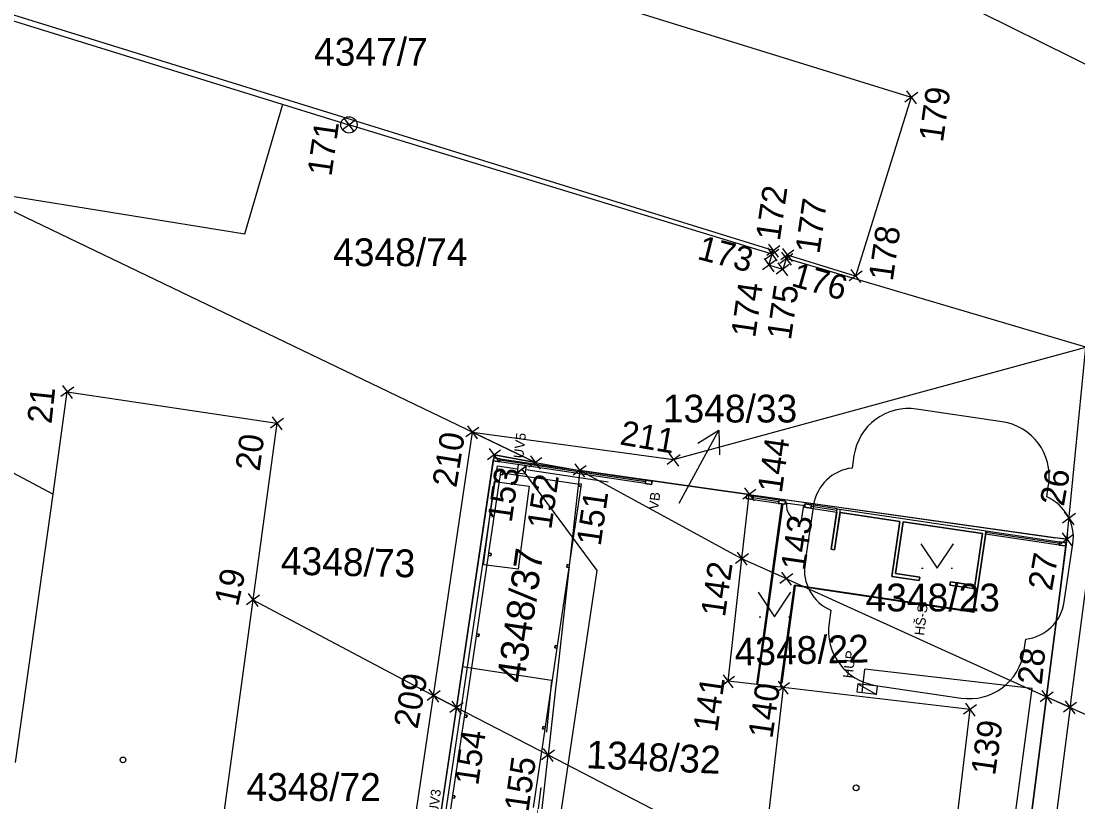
# Model space of a CAD drawing. Extents: x -735036 to -734743, y -1144813 to -1144181.
# Drawn here: x -734897 to -734832.3, y -1144527.8 to -1144480 of the extents above; entities that cross this region are included whole.
import ezdxf

# ---------------------------------------------------------------- set-up
doc = ezdxf.new("R2010")
doc.units = 0
for name, color, linetype in [('A3_BOURANÉ OBJEKTY', 7, 'Continuous'), ('A3_Netisk', 7, 'Continuous'), ('A3_ODVODŇOVACÍ ŽLAB', 7, 'Continuous'), ('A3_SIT_OBJEKTY_N01', 7, 'Continuous'), ('A3_SIT_PNB', 7, 'Continuous'), ('CKKOTY', 7, 'Continuous'), ('CKPLYN_POTRUBI_NT_PODZ_N', 7, 'Continuous'), ('CKTEXTY_MALE', 7, 'Continuous'), ('Groma (60)', 7, 'Continuous'), ('hranice pl. určené SŽDC', 7, 'Continuous'), ('Katastr_HRANICE DRÁHY', 7, 'Continuous'), ('Katastr_Hranice parcel', 7, 'Continuous'), ('Katastr_Parcelní čísla', 7, 'Continuous'), ('Katastr_Značky kultur', 7, 'Continuous'), ('SO05_CKKANALIZACE_JEDNOTNA_PODZ_N', 7, 'Continuous'), ('ZÁBORY_dočasné', 7, 'Continuous')]:
    doc.layers.add(name, color=color, linetype=linetype)

# ---------------------------------------------------------------- blocks, each defined once
blk = doc.blocks.new('POINT_DISPLAY')
for p, q in [((-0.35, -0.35), (0.35, 0.35)), ((-0.35, 0.35), (0.35, -0.35))]:
    blk.add_line(p, q)

msp = doc.modelspace()

# ---------------------------------------------------------------- linework, layer by layer
msp.add_line((-734866.625, -1144507.658), (-734866.057, -1144507.237))
for points in [[(-734866.625, -1144507.658), (-734866.13, -1144507.731), (-734866.057, -1144507.237), (-734866.551, -1144507.163)], [(-734866.625, -1144507.658), (-734866.13, -1144507.731), (-734866.057, -1144507.237)]]:
    msp.add_lwpolyline(points, close=True)
at = {"layer": 'A3_BOURANÉ OBJEKTY'}
msp.add_lwpolyline([(-734866.552, -1144513.548), (-734868.669, -1144513.299), (-734867.996, -1144508.198), (-734865.894, -1144508.483)], close=True, dxfattribs=at)
for points in [[(-734869.977, -1144519.507), (-734864.523, -1144520.336), (-734864.819, -1144523.525)], [(-734865.166, -1144526.906), (-734865.978, -1144533.409), (-734871.807, -1144532.846)]]:
    msp.add_lwpolyline(points, dxfattribs=at)
at = {"layer": 'A3_Netisk'}
msp.add_line((-734838.465, -1144514.774), (-734837.936, -1144511.213), dxfattribs=at)
at = {"layer": 'A3_ODVODŇOVACÍ ŽLAB'}
for points in [[(-734870.972, -1144528.414), (-734867.824, -1144507.227), (-734866.588, -1144507.411)], [(-734861.049, -1144508.234), (-734866.093, -1144507.484)]]:
    msp.add_lwpolyline(points, dxfattribs=at)
at = {"layer": 'A3_SIT_OBJEKTY_N01'}
for p, q in [((-734867.491, -1144507.64), (-734867.62, -1144507.621)), ((-734867.487, -1144507.681), (-734867.483, -1144507.651)), ((-734862.694, -1144508.352), (-734862.823, -1144508.333)), ((-734851.963, -1144520.613), (-734850.421, -1144509.56)), ((-734850.371, -1144509.567), (-734851.914, -1144520.619)), ((-734850.626, -1144509.529), (-734850.597, -1144509.332)), ((-734850.23, -1144509.588), (-734850.626, -1144509.529)), ((-734850.597, -1144509.332), (-734850.201, -1144509.39)), ((-734850.421, -1144509.56), (-734850.371, -1144509.567)), ((-734850.201, -1144509.39), (-734850.23, -1144509.588)), ((-734849.043, -1144509.765), (-734849.014, -1144509.567)), ((-734848.648, -1144509.823), (-734849.043, -1144509.765)), ((-734849.014, -1144509.567), (-734848.618, -1144509.626)), ((-734848.618, -1144509.626), (-734848.648, -1144509.823)), ((-734847.403, -1144512.334), (-734847.036, -1144509.861)), ((-734846.867, -1144510.088), (-734847.205, -1144512.363)), ((-734847.036, -1144509.861), (-734837.936, -1144511.213)), ((-734843.207, -1144510.632), (-734846.867, -1144510.088)), ((-734843.707, -1144513.995), (-734843.207, -1144510.632)), ((-734843.01, -1144510.661), (-734843.48, -1144513.826)), ((-734838.163, -1144511.381), (-734843.01, -1144510.661)), ((-734838.633, -1144514.546), (-734838.163, -1144511.381)), ((-734837.936, -1144511.213), (-734838.465, -1144514.774)), ((-734847.205, -1144512.363), (-734847.403, -1144512.334)), ((-734842.026, -1144514.245), (-734843.707, -1144513.995)), ((-734843.48, -1144513.826), (-734841.996, -1144514.047)), ((-734841.996, -1144514.047), (-734842.026, -1144514.245)), ((-734850.488, -1144520.532), (-734849.65, -1144514.527)), ((-734849.607, -1144514.584), (-734850.438, -1144520.538)), ((-734849.65, -1144514.527), (-734838.72, -1144516.151)), ((-734838.678, -1144516.208), (-734849.607, -1144514.584)), ((-734840.146, -1144514.524), (-734840.117, -1144514.326)), ((-734838.465, -1144514.774), (-734840.146, -1144514.524)), ((-734840.117, -1144514.326), (-734838.633, -1144514.546)), ((-734838.72, -1144516.151), (-734838.514, -1144514.766)), ((-734838.465, -1144514.774), (-734838.678, -1144516.208)), ((-734838.514, -1144514.766), (-734838.465, -1144514.774)), ((-734851.914, -1144520.619), (-734851.963, -1144520.613)), ((-734850.438, -1144520.538), (-734850.488, -1144520.532))]:
    msp.add_line(p, q, dxfattribs=at)
for points in [[(-734888.44, -1144569.554), (-734887.65, -1144563.8), (-734885.58, -1144548.75), (-734874.6, -1144550.79), (-734868.084, -1144506.936)], [(-734867.659, -1144506.797), (-734867.689, -1144506.994), (-734868.084, -1144506.936), (-734868.055, -1144506.738), (-734867.659, -1144506.797)], [(-734858.772, -1144508.218), (-734867.674, -1144506.895)], [(-734865.623, -1144528.137), (-734864.911, -1144523.339), (-734865.059, -1144523.317), (-734865.037, -1144523.169), (-734864.889, -1144523.191), (-734864.176, -1144518.394), (-734864.324, -1144518.372), (-734864.302, -1144518.223), (-734864.154, -1144518.245), (-734863.441, -1144513.448), (-734863.589, -1144513.426), (-734863.567, -1144513.278), (-734863.419, -1144513.3), (-734862.706, -1144508.502), (-734862.855, -1144508.48), (-734862.838, -1144508.372), (-734862.937, -1144508.357), (-734867.389, -1144507.696), (-734867.487, -1144507.681), (-734867.504, -1144507.79), (-734867.652, -1144507.767), (-734868.365, -1144512.565), (-734868.216, -1144512.587), (-734868.238, -1144512.735), (-734868.387, -1144512.713), (-734869.099, -1144517.511), (-734868.951, -1144517.533), (-734868.973, -1144517.681), (-734869.122, -1144517.659), (-734869.834, -1144522.456), (-734869.686, -1144522.478), (-734869.708, -1144522.627), (-734869.856, -1144522.605), (-734870.569, -1144527.402), (-734870.421, -1144527.424), (-734870.443, -1144527.572), (-734870.591, -1144527.55), (-734871.304, -1144532.348)], [(-734867.631, -1144507.629), (-734867.652, -1144507.767), (-734867.504, -1144507.79), (-734867.487, -1144507.681)], [(-734862.834, -1144508.342), (-734862.838, -1144508.372), (-734862.855, -1144508.48), (-734862.706, -1144508.502), (-734862.686, -1144508.364)], [(-734858.391, -1144508.376), (-734858.786, -1144508.317), (-734858.757, -1144508.119), (-734858.361, -1144508.178), (-734858.391, -1144508.376)], [(-734852.209, -1144509.294), (-734852.604, -1144509.236), (-734852.575, -1144509.038), (-734852.179, -1144509.097), (-734852.209, -1144509.294)], [(-734850.611, -1144509.431), (-734852.194, -1144509.195)], [(-734850.136, -1144509.501), (-734850.216, -1144509.489)], [(-734849.029, -1144509.666), (-734849.108, -1144509.654), (-734849.261, -1144510.683)], [(-734847.05, -1144509.96), (-734848.633, -1144509.724)], [(-734833.45, -1144511.98), (-734837.95, -1144511.312)], [(-734833.069, -1144512.138), (-734834.23, -1144521.36), (-734836.63, -1144539.96), (-734838.79, -1144556.7), (-734840.06, -1144566.59), (-734840.228, -1144567.714), (-734841.06, -1144574.32)], [(-734833.069, -1144512.138), (-734833.464, -1144512.079), (-734833.435, -1144511.881), (-734833.039, -1144511.94), (-734833.069, -1144512.138)], [(-734868.216, -1144512.587), (-734868.365, -1144512.565), (-734868.387, -1144512.713), (-734868.238, -1144512.735), (-734868.216, -1144512.587)], [(-734863.419, -1144513.3), (-734863.567, -1144513.278), (-734863.589, -1144513.426), (-734863.441, -1144513.448), (-734863.419, -1144513.3)], [(-734868.951, -1144517.533), (-734869.099, -1144517.511), (-734869.122, -1144517.659), (-734868.973, -1144517.681), (-734868.951, -1144517.533)], [(-734864.154, -1144518.245), (-734864.302, -1144518.223), (-734864.324, -1144518.372), (-734864.176, -1144518.394), (-734864.154, -1144518.245)], [(-734869.686, -1144522.478), (-734869.834, -1144522.456), (-734869.856, -1144522.605), (-734869.708, -1144522.627), (-734869.686, -1144522.478)], [(-734864.889, -1144523.191), (-734865.037, -1144523.169), (-734865.059, -1144523.317), (-734864.911, -1144523.339), (-734864.889, -1144523.191)], [(-734870.421, -1144527.424), (-734870.569, -1144527.402), (-734870.591, -1144527.55), (-734870.443, -1144527.572), (-734870.421, -1144527.424)]]:
    msp.add_lwpolyline(points, dxfattribs=at)
for points in [[(-734868.055, -1144506.738), (-734868.084, -1144506.936), (-734867.689, -1144506.994), (-734867.659, -1144506.797)], [(-734867.659, -1144506.797), (-734858.757, -1144508.119), (-734858.786, -1144508.317), (-734867.689, -1144506.994)], [(-734858.786, -1144508.317), (-734858.391, -1144508.376), (-734858.361, -1144508.178), (-734858.757, -1144508.119)], [(-734852.604, -1144509.236), (-734852.209, -1144509.294), (-734852.179, -1144509.097), (-734852.575, -1144509.038)], [(-734852.604, -1144509.236), (-734850.23, -1144509.588), (-734850.201, -1144509.39), (-734852.575, -1144509.038)], [(-734851.914, -1144520.619), (-734851.963, -1144520.613), (-734850.421, -1144509.56), (-734850.371, -1144509.567)], [(-734850.488, -1144520.532), (-734850.517, -1144520.781), (-734851.914, -1144520.619), (-734850.371, -1144509.567), (-734850.23, -1144509.588), (-734850.216, -1144509.489), (-734849.029, -1144509.666), (-734849.043, -1144509.765), (-734847.065, -1144510.059), (-734847.403, -1144512.334), (-734847.205, -1144512.363), (-734846.867, -1144510.088), (-734843.207, -1144510.632), (-734843.707, -1144513.995), (-734842.026, -1144514.245), (-734841.996, -1144514.047), (-734843.48, -1144513.826), (-734843.01, -1144510.661), (-734838.163, -1144511.381), (-734838.633, -1144514.546), (-734840.117, -1144514.326), (-734840.146, -1144514.524), (-734838.514, -1144514.766), (-734838.72, -1144516.151), (-734838.72, -1144516.151), (-734849.65, -1144514.527)], [(-734850.626, -1144509.529), (-734850.23, -1144509.588), (-734850.201, -1144509.39), (-734850.201, -1144509.39), (-734850.597, -1144509.332)], [(-734849.014, -1144509.567), (-734849.043, -1144509.765), (-734848.648, -1144509.823), (-734848.618, -1144509.626)], [(-734847.036, -1144509.861), (-734848.618, -1144509.626), (-734848.648, -1144509.823), (-734847.065, -1144510.059)], [(-734842.026, -1144514.245), (-734843.707, -1144513.995), (-734843.207, -1144510.632), (-734846.867, -1144510.088), (-734847.205, -1144512.363), (-734847.403, -1144512.334), (-734847.036, -1144509.861), (-734837.936, -1144511.213), (-734838.465, -1144514.774), (-734840.146, -1144514.524), (-734840.117, -1144514.326), (-734838.633, -1144514.546), (-734838.163, -1144511.381), (-734843.01, -1144510.661), (-734843.48, -1144513.826), (-734841.996, -1144514.047)], [(-734833.464, -1144512.079), (-734837.965, -1144511.411), (-734837.936, -1144511.213), (-734833.435, -1144511.881)], [(-734833.464, -1144512.079), (-734833.069, -1144512.138), (-734833.039, -1144511.94), (-734833.435, -1144511.881)], [(-734838.465, -1144514.774), (-734838.678, -1144516.208), (-734849.607, -1144514.584), (-734850.438, -1144520.538), (-734850.488, -1144520.532), (-734849.65, -1144514.527), (-734838.72, -1144516.151), (-734838.514, -1144514.766)]]:
    msp.add_lwpolyline(points, close=True, dxfattribs=at)
for centre, radius, start, end in [((-734867.621, -1144507.63), 0.01, 81.54908, 171.54908), ((-734867.493, -1144507.65), 0.01, 351.54908, 81.54908), ((-734862.824, -1144508.343), 0.01, 81.54908, 171.54908), ((-734862.695, -1144508.362), 0.01, 351.54908, 81.54908), ((-734849.108, -1144509.654), 1.04, 171.54994, 261.54908)]:
    msp.add_arc(centre, radius, start, end, dxfattribs=at)
at = {"layer": 'A3_SIT_PNB'}
for points in [[(-734836.945, -1144504.546), (-734842.187, -1144503.767)], [(-734846.016, -1144506.605), (-734846.13, -1144507.371)], [(-734834.221, -1144509.14), (-734834.107, -1144508.375)], [(-734848.49, -1144509.645), (-734849.019, -1144513.206)], [(-734833.153, -1144515.563), (-734832.624, -1144512.002)], [(-734847.422, -1144516.067), (-734847.536, -1144516.833)], [(-734835.626, -1144518.602), (-734835.513, -1144517.837)], [(-734844.698, -1144520.662), (-734839.455, -1144521.44)]]:
    msp.add_lwpolyline(points, dxfattribs=at)
for centre, radius, start, end in [((-734842.683, -1144507.1), 3.37, 81.54908, 171.54908), ((-734837.44, -1144507.879), 3.37, 351.54908, 81.54908), ((-734845.834, -1144510.039), 2.685, 96.32984, 171.54908), ((-734835.28, -1144511.607), 2.685, 351.54908, 66.76833), ((-734846.363, -1144513.6), 2.685, 171.54908, 246.76833), ((-734835.809, -1144515.168), 2.685, 276.32984, 351.54908), ((-734844.202, -1144517.328), 3.37, 171.54908, 261.54908), ((-734838.96, -1144518.107), 3.37, 261.54908, 351.54908)]:
    msp.add_arc(centre, radius, start, end, dxfattribs=at)
at = {"layer": 'CKKOTY'}
msp.add_line((-734847.205, -1144512.363), (-734846.838, -1144509.89), dxfattribs=at)
at = {"layer": 'CKPLYN_POTRUBI_NT_PODZ_N'}
msp.add_line((-734845.514, -1144521.105), (-734845.346, -1144519.67), dxfattribs=at)
msp.add_lwpolyline([(-734840.638, -1144562.238), (-734835.108, -1144520.855), (-734845.346, -1144519.67)], dxfattribs=at)
for points in [[(-734844.641, -1144521.205), (-734844.583, -1144520.71), (-734845.775, -1144520.57), (-734845.833, -1144521.066)], [(-734844.633, -1144521.222), (-734844.583, -1144520.71), (-734845.773, -1144520.571)]]:
    msp.add_lwpolyline(points, close=True, dxfattribs=at)
at = {"layer": 'hranice pl. určené SŽDC'}
for p, q in [((-734883.27, -1144493.05), (-734880.96, -1144485.12)), ((-734900.35, -1144490.28), (-734883.27, -1144493.05))]:
    msp.add_line(p, q, dxfattribs=at)
at = {"layer": 'Katastr_HRANICE DRÁHY'}
msp.add_line((-734861.21, -1144468.1), (-734830.02, -1144483.57), dxfattribs=at)
for points in [[(-734832.95, -1144511.4), (-734831.84, -1144499.97)], [(-734895.01, -1144508.96), (-734894.14, -1144502.71)], [(-734894.14, -1144502.71), (-734881.31, -1144504.63)], [(-734881.31, -1144504.63), (-734882.78, -1144515.44)], [(-734897.31, -1144525.39), (-734895.01, -1144508.96)], [(-734832.99, -1144511.73), (-734832.95, -1144511.4)], [(-734834.23, -1144521.36), (-734832.99, -1144511.73)], [(-734882.78, -1144515.44), (-734885, -1144531.74)], [(-734836.63, -1144539.96), (-734834.23, -1144521.36)]]:
    msp.add_lwpolyline(points, dxfattribs=at)
at = {"layer": 'Katastr_Hranice parcel'}
for points in [[(-734902.72, -1144466.02), (-734842.51, -1144484.69)], [(-734917.71, -1144473.71), (-734876.91, -1144486.38)], [(-734850.95, -1144494.07), (-734906.11, -1144476.96)], [(-734942.87, -1144483.49), (-734895.01, -1144508.96)], [(-734865.5, -1144507.03), (-734912.56, -1144484.42)], [(-734842.51, -1144484.69), (-734845.92, -1144495.63)], [(-734851.02, -1144494.29), (-734876.91, -1144486.38)], [(-734850.95, -1144494.07), (-734851.02, -1144494.29)], [(-734851.22, -1144494.96), (-734851.02, -1144494.29)], [(-734850.16, -1144494.56), (-734850.37, -1144495.22)], [(-734850.09, -1144494.34), (-734850.16, -1144494.56)], [(-734831.84, -1144499.97), (-734850.16, -1144494.56)], [(-734845.92, -1144495.63), (-734850.09, -1144494.34)], [(-734850.37, -1144495.22), (-734851.22, -1144494.96)], [(-734868.03, -1144506.57), (-734870.33, -1144522.02)], [(-734868.03, -1144506.57), (-734865.5, -1144507.03)], [(-734865.5, -1144507.03), (-734862.79, -1144507.52)], [(-734862.79, -1144507.52), (-734864.73, -1144524.92)], [(-734852.42, -1144508.98), (-734862.79, -1144507.52)], [(-734852.87, -1144512.92), (-734862.79, -1144507.52)], [(-734852.87, -1144512.92), (-734852.42, -1144508.98)], [(-734852.42, -1144508.98), (-734833.68, -1144511.64)], [(-734832.99, -1144511.73), (-734833.68, -1144511.64)], [(-734853.72, -1144520.41), (-734852.87, -1144512.92)], [(-734850.22, -1144514.11), (-734852.87, -1144512.92)], [(-734850.22, -1144514.11), (-734834.23, -1144521.36)], [(-734882.78, -1144515.44), (-734872.29, -1144521)], [(-734850.35, -1144520.8), (-734853.72, -1144520.41)], [(-734872.29, -1144521), (-734870.33, -1144522.02)], [(-734850.35, -1144520.8), (-734851.62, -1144531.72)], [(-734838.91, -1144522.14), (-734850.35, -1144520.8)], [(-734834.23, -1144521.36), (-734830.38, -1144523.1)], [(-734870.33, -1144522.02), (-734872.73, -1144538.19)], [(-734870.33, -1144522.02), (-734864.73, -1144524.92)], [(-734840.76, -1144537.68), (-734838.91, -1144522.14)], [(-734866.58, -1144541.54), (-734864.73, -1144524.92)], [(-734864.73, -1144524.92), (-734851.62, -1144531.72)]]:
    msp.add_lwpolyline(points, dxfattribs=at)
at = {"layer": 'Katastr_Parcelní čísla'}
for p, q in [((-734855.563, -1144505.849), (-734854.284, -1144505.063)), ((-734856.7, -1144509.52), (-734856.19, -1144508.58))]:
    msp.add_line(p, q, dxfattribs=at)
msp.add_lwpolyline([(-734856.19, -1144508.58), (-734854.284, -1144505.063), (-734854.244, -1144506.563)], dxfattribs=at)
at = {"layer": 'Katastr_Značky kultur'}
for p, q in [((-734876.96, -1144486.38), (-734876.86, -1144486.38)), ((-734841.88, -1144513.5), (-734841.78, -1144513.5)), ((-734840.08, -1144513.5), (-734839.98, -1144513.5)), ((-734851.82, -1144516.47), (-734851.72, -1144516.47)), ((-734850.02, -1144516.47), (-734849.92, -1144516.47))]:
    msp.add_line(p, q, dxfattribs=at)
for points in [[(-734841.93, -1144512), (-734840.93, -1144513.5), (-734839.93, -1144512)], [(-734851.87, -1144514.97), (-734850.87, -1144516.47), (-734849.87, -1144514.97)]]:
    msp.add_lwpolyline(points, dxfattribs=at)
for centre, radius in [((-734876.91, -1144486.38), 0.499), ((-734890.73, -1144525.22), 0.175), ((-734845.89, -1144526.93), 0.175)]:
    msp.add_circle(centre, radius, dxfattribs=at)
at = {"layer": 'SO05_CKKANALIZACE_JEDNOTNA_PODZ_N'}
msp.add_lwpolyline([(-734866.341, -1144507.447), (-734861.751, -1144513.639), (-734864.21, -1144530.193), (-734864.357, -1144531.183), (-734866.393, -1144544.885), (-734866.467, -1144545.379), (-734868.027, -1144555.885), (-734873.869, -1144554.902)], dxfattribs=at)
at = {"layer": 'ZÁBORY_dočasné'}
for p, q in [((-734857.053, -1144506.856), (-734831.84, -1144499.97)), ((-734832.95, -1144511.4), (-734831.84, -1144499.97)), ((-734871.733, -1144521.29), (-734869.357, -1144505.177)), ((-734869.357, -1144505.177), (-734865.5, -1144507.03)), ((-734869.357, -1144505.177), (-734857.053, -1144506.856)), ((-734868.03, -1144506.57), (-734870.33, -1144522.02)), ((-734865.5, -1144507.03), (-734868.03, -1144506.57)), ((-734865.5, -1144507.03), (-734862.79, -1144507.52)), ((-734862.79, -1144507.52), (-734852.42, -1144508.98)), ((-734852.42, -1144508.98), (-734832.99, -1144511.73)), ((-734832.95, -1144511.4), (-734832.99, -1144511.73)), ((-734832.99, -1144511.73), (-734834.23, -1144521.36)), ((-734874.131, -1144537.425), (-734871.733, -1144521.29)), ((-734870.33, -1144522.02), (-734871.733, -1144521.29)), ((-734836.63, -1144539.96), (-734834.23, -1144521.36)), ((-734834.23, -1144521.36), (-734832.801, -1144522.006)), ((-734870.326, -1144522.022), (-734872.73, -1144538.19))]:
    msp.add_line(p, q, dxfattribs=at)
for points in [[(-734831.496, -1144511.942), (-734832.742, -1144521.55), (-734832.801, -1144522.006)], [(-734832.801, -1144522.006), (-734832.801, -1144522.006), (-734835.142, -1144540.152), (-734835.218, -1144540.74)]]:
    msp.add_lwpolyline(points, dxfattribs=at)

# ---------------------------------------------------------------- block references
at = {"layer": 'Groma (60)', "rotation": -98.65482414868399}
for p in [(-734842.51, -1144484.69), (-734876.91, -1144486.38), (-734851.02, -1144494.296), (-734850.95, -1144494.07), (-734850.16, -1144494.56), (-734850.09, -1144494.34), (-734851.22, -1144494.96), (-734850.37, -1144495.22), (-734845.92, -1144495.63), (-734894.14, -1144502.71), (-734881.31, -1144504.63), (-734869.357, -1144505.177), (-734868.03, -1144506.57), (-734857.053, -1144506.856), (-734865.5, -1144507.03), (-734862.79, -1144507.52), (-734852.42, -1144508.98), (-734832.858, -1144510.449), (-734832.99, -1144511.73), (-734852.87, -1144512.92), (-734850.16, -1144514.143), (-734882.78, -1144515.44), (-734853.72, -1144520.41), (-734850.35, -1144520.8), (-734871.733, -1144521.29), (-734834.231, -1144521.37), (-734870.33, -1144522.02), (-734838.91, -1144522.14), (-734832.802, -1144522.006), (-734864.73, -1144524.92)]:
    msp.add_blockref('POINT_DISPLAY', p, dxfattribs=at)

# ---------------------------------------------------------------- texts
at = {"layer": 'CKTEXTY_MALE'}
for s, p in [('UV5', (-734866.251, -1144506.804)), ('VB', (-734857.985, -1144509.937)), ('HŠ-S', (-734841.727, -1144517.637)), ('HUP', (-734846.102, -1144520.255)), ('UV3', (-734871.455, -1144528.601))]:
    msp.add_text(s, height=0.6, rotation=83.326, dxfattribs=at).set_placement(p)
at = {"layer": 'Groma (60)'}
for s, rotation, p in [('179', 81.78352, (-734840.577, -1144487.488)), ('171', 81.78352, (-734877.982, -1144489.571)), ('172', 81.78352, (-734850.557, -1144493.527)), ('177', 81.78352, (-734848.134, -1144494.316)), ('178', 81.78352, (-734843.647, -1144495.984)), ('173', 345.49731, (-734855.664, -1144494.574)), ('176', 344.06447, (-734849.914, -1144496.21)), ('174', 81.78352, (-734852.063, -1144499.442)), ('175', 81.78352, (-734849.876, -1144499.587)), ('21', 84.03675, (-734895.102, -1144504.699)), ('211', 350.16241, (-734860.394, -1144505.918)), ('210', 80.85728, (-734870.341, -1144508.614)), ('20', 82.27085, (-734882.38, -1144507.61)), ('144', 81.78352, (-734850.437, -1144508.944)), ('153', 81.78352, (-734866.957, -1144510.749)), ('152', 81.78352, (-734864.535, -1144511.169)), ('26', 79.9599, (-734833.181, -1144509.754)), ('151', 81.78352, (-734861.516, -1144512.186)), ('143', 81.78352, (-734849.016, -1144513.698)), ('27', 79.9599, (-734833.908, -1144514.925)), ('19', 77.33431, (-734883.704, -1144515.892)), ('142', 81.78352, (-734853.911, -1144516.53)), ('28', 84.09401, (-734834.53, -1144520.665)), ('209', 79.05597, (-734872.718, -1144523.376)), ('141', 81.78352, (-734854.381, -1144523.571)), ('140', 81.78352, (-734851.011, -1144523.961)), ('139', 81.78352, (-734837.391, -1144526.219)), ('154', 81.78352, (-734869.006, -1144526.829)), ('155', 81.78352, (-734865.933, -1144528.453))]:
    msp.add_text(s, height=1.5, rotation=rotation, dxfattribs=at).set_placement(p)
at = {"layer": 'Katastr_Parcelní čísla'}
for s, p in [('4347/7', (-734879.043, -1144482.76)), ('4348/74', (-734877.873, -1144495.02)), ('1348/33', (-734857.704, -1144504.583)), ('4348/23', (-734845.307, -1144516.14)), ('4348/72', (-734883.177, -1144527.73))]:
    msp.add_text(s, height=1.7, dxfattribs=at).set_placement(p)
for s, rotation, p in [('4348/73', 358.76214, (-734881.086, -1144513.882)), ('4348/37', 81.65502, (-734866.195, -1144520.566)), ('4348/22', 1.45107, (-734853.296, -1144519.463)), ('1348/32', 357.57765, (-734862.418, -1144525.727))]:
    msp.add_text(s, height=1.7, rotation=rotation, dxfattribs=at).set_placement(p)

doc.saveas('drawing.dxf')
